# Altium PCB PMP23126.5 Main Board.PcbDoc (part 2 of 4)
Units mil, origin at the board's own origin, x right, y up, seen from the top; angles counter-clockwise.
Board outline 7480.32 x 4667 mil, 6 copper layers (Top Layer, Signal Layer 1, Signal Layer 2, Signal Layer 3, Signal Layer 4, Bottom Layer), stack 65.8 mil thick; 166 components, 83 nets, 633 pads, 4418 vias.
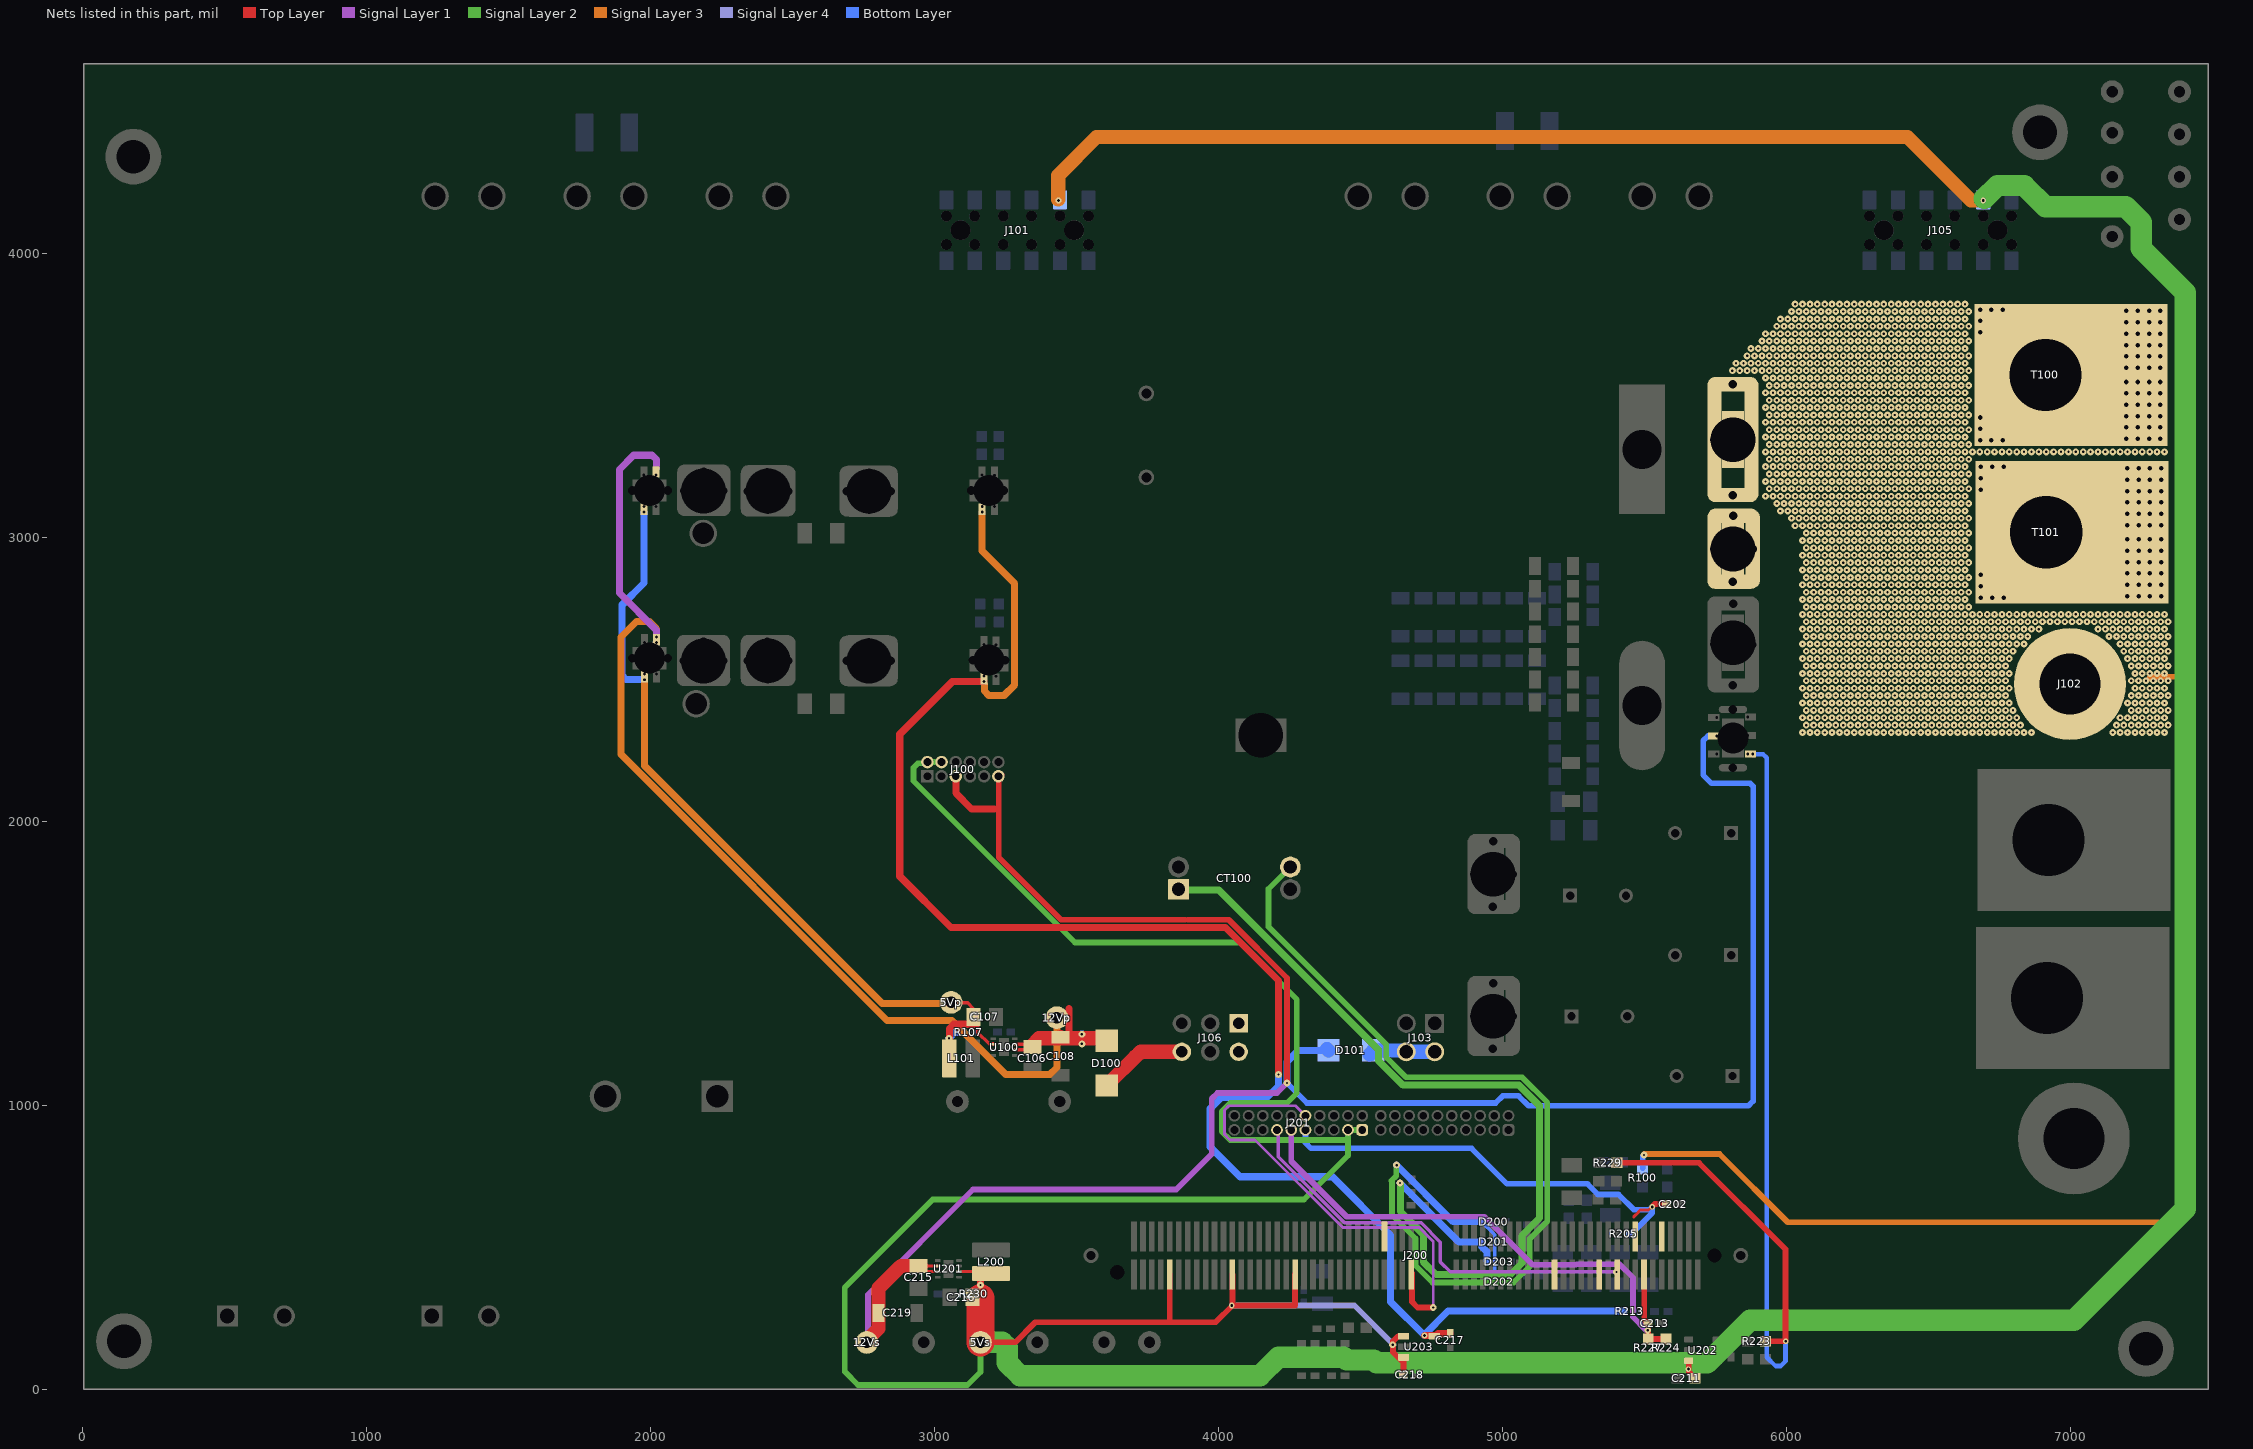
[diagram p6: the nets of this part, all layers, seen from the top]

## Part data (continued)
C205: library part CMP-0006320-2, "CAP, CERM, 470 pF, 50 V, +/- 10%, X7R, AEC-Q200 Grade 1, 0402", Cap_Case=0402, Manufacturer=TDK, Supplier Part Number 1=445-6888-1-ND, TempCo=X7R, Tolerance_%=10%, Value1="4.96489 ohm", Value2=50V, ValueDisplayed=470pF
C210 C214: "CAP, CERM, 1000pF, 50V, +/-10%, C0G/NP0, 0603", Cap_Case=0603, Manufacturer=AVX, Supplier Part Number 1=478-3718-1-ND, TempCo=C0G/NP0, Tolerance_%=10, Value1="0.048 ohm", Value2=50V, ValueDisplayed=1000pF
C211: "CAP, CERM, 1uF, 25V, +/-10%, X7R, 0603", Cap_Case=0603, Manufacturer=TDK, Supplier Part Number 1=445-5956-1-ND, TempCo=X7R, Tolerance_%=10, Value1=Unknown, Value2=25V, ValueDisplayed=1uF
C212: "CAP, CERM, 4.7 pF, 25 V,+/- 5%, C0G/NP0, 0402", Cap_Case=0402, Manufacturer=MuRata, Supplier Part Number 1=81-GRM1555C1E4R7CA1D, TempCo=C0G/NP0, Tolerance_%=5, Value2=25V, ValueDisplayed=4.7pF
C213: library part CMP-0064911-2, "CAP, CERM, 10 pF, 50 V,+/- 2.5%, C0G/NP0, AEC-Q200 Grade 1, 0402", Cap_Case=0402, Manufacturer=AVX, Supplier Part Number 1=478-5991-1-ND, TempCo=C0G/NP0, Tolerance_%=2.5%, Value1=Unknown, Value2=50V, ValueDisplayed=10pF
C217 C218: "CAP, CERM, 0.1uF, 6.3V, +/-10%, X7R, 0402", Cap_Case=0402, Manufacturer=MuRata, Supplier Part Number 1=GRM155R70J104KA01D-ND, TempCo=X7R, Tolerance_%=10, Value1=Unknown, Value2=6.3V, ValueDisplayed=0.1uF
C300 C301 C302 C303 C304 C315 C316 C317 C318 C319 C325 C326 C327 C328 C329 C330 C331 C332 C333 C334: library part CMP-0064950-2, "CAP, CERM, 0.1 uF, 25 V,+/- 5%, C0G/NP0, 1206", Cap_Case=1206, Manufacturer=MuRata, Supplier Part Number 1=490-1767-1-ND, TempCo=C0G/NP0, Tolerance_%=5%, Value1=Unknown, Value2=25V, ValueDisplayed=0.1uF
C305 C306 C307 C308 C309 C320 C321 C322 C323 C324: library part CMP-0008656-2, "CAP, CERM, 47 uF, 25 V, +/- 20%, X5R, 1206_190", Cap_Case=1206, Manufacturer=TDK, Supplier Part Number 1=445-8047-1-ND, TempCo=X5R, Tolerance_%=20%, Value1=Unknown, Value2=25V, ValueDisplayed=47uF
C310 C311 C312 C313 C314: library part CMP-0094633-1, "2200 µF 16 V Aluminum - Polymer Capacitors Radial, Can 8mOhm 20000 Hrs @ 105°C", Digikey Part Number=565-4315-ND, Leakage Current=7040uA, Manufacturer="United Chemi-Con", Mouser Part Number=661-APSG160E222MJ20S, Operating Temperature Range="-55°C to +105°C", Tolerance_%=20%, ValueDisplayed=2200uF
CT100: library part CMP-0091119-1, "Inductor PTH 3.3mH 300mOhm", Manufacturer="Pulse Electronics", Operating Temperature Range="-40°C to +125°C", Test Frequency=100kHz
D100 D101: library part CMP-0028374-2, "Diode, Schottky, 20 V, 1 A, SMA", Manufacturer="Diodes Inc.", Value1=1A, Value2=0.5V
D200 D201 D202 D203: "Diode, Ultrafast, 100 V, 0.25 A, SOD-323", Manufacturer=Nexperia, Supplier Part Number 1=568-5003-1-ND, Value1=0.25A, Value2=1.4V
J100: library part CMP-0094055-1, "12 Position Receptacle Connector 0.050\" (1.27mm) Through Hole Gold", Current_A=1A, Digikey Part Number=952-1366-5-ND, Manufacturer=Harwin, Mouser Part Number=855-M50-3000645, Operating Temperature Range="-40°C to +105°C"
J101 J105: library part CMP-0089984-1, "12 Position Receptacle, Bottom Entry Connector  Surface Mount", Current_A=4.1A, Digikey Part Number=HLE-106-02-G-DV-BE-A-ND, Manufacturer=Samtec, Mouser Part Number=200-HLE10602GDVBEA, Operating Temperature Range="-55°C to +125°C", Voltage_V=400V
J102 J104: library part CMP-0055165-2, "Standard Banana Jack, Uninsulated, 5.5mm", Manufacturer=Keystone, Supplier Part Number 1=36-575-4-ND
J103: library part CMP-0054598-1, "Header, 2.54mm, 2x2, Gold, TH", Color=Black, Current_A=3A, Manufacturer="Sullins Connector Solutions", Supplier Part Number 1=S2011E-02-ND, Voltage_V=1.8kV
J106: library part CMP-0054565-2, "Header, 100mil, 3x2, Gold, TH", Color=Black, Current_A=3A, Manufacturer="Sullins Connector Solutions", Supplier Part Number 1=S2011E-03-ND, Voltage_V=1.8kV
J200: library part controlCARD-120HSEC, "C2000 controlCARD-120HSEC connector, SMT", Manufacturer=Samtec
J201 J202: library part CMP-0750170-1, "Header, 1.27mm, 10x2, Gold, TH", Color=Black, Current_A=1A, Manufacturer="Sullins Connector Solutions", Voltage_V=500V
L100: library part CMP-0093530-1, "INDUCTOR, POWER, EP33, TH 0.42uH 20% 10kHz 0.06mOhm DCR MAX 300A Isat", Manufacturer=Pulse, Operating Temperature Range="-40°C to +125°C", Test Frequency=10kHz, Tolerance_%=20%
L101 L200: library part CMP-0087867-1, "2.2µH Shielded Molded Inductor 2.4A 67mOhm Max 2-SMD", Manufacturer="Wurth Electronics"
LEG1_HS LEG1_LS LEG2_HS LEG2_LS: "Test Point, Miniature, Yellow, TH", Color=Yellow, Manufacturer=Keystone, Supplier Part Number 1=36-5004-ND
LOGO100: library part CMP-0074837-1, "IEC 61010-1 Hot Surface Warning"
LOGO101: library part CMP-0074835-1, "IEC 61010-1 High Voltage Warning"
Logo102: library part CMP-0074847-1, "FCC_disclaimer"
Logo103: library part CMP-0074769-1
PGND PGND SGND SGND SGND SGND SGND101 SGND102 SGND103: "Test Point, Miniature, Black, TH", Color=Black, Manufacturer=Keystone, Supplier Part Number 1=36-5001-ND
PGND Vin: library part CMP-0055471-1, "Terminal Block, 5.08 mm, 2x1, TH", Color=Green, Current_A=17.5A, Manufacturer="Phoenix Contact", Supplier Part Number 1=277-1263-ND, Voltage_V=400V
PSON: "Test Point, Miniature, Orange, TH", Color=Orange, Manufacturer=Keystone, Supplier Part Number 1=36-5003-ND
R100 R101: "RES, 243, 1%, 0.1 W, 0603", Manufacturer=Vishay-Dale, Power_W=0.1, Supplier Part Number 1=541-243HCT-ND, TempCo="100 ppm/C", Tolerance_%=1, Value1=1%, Value2=0.1W, Value_Code=243R, ValueDisplayed=243
R102 R103: library part CMP-0018389-2, "RES, 5.11 k, 1%, 0.25 W, 1206", Manufacturer="Yageo America", Power_W=250mW, Supplier Part Number 1=311-5.11KFRCT-ND, TempCo="100 ppm/C", Tolerance_%=1%, Value2=0.25W, Value_Code=5k11, ValueDisplayed=5.11k
R104 R105 R106 R108: "RES, 0, 5%, 0.1 W, 0603", Manufacturer=Vishay-Dale, Power_W=0.1, Supplier Part Number 1=541-0.0GCT-ND, TempCo="200 ppm/C", Tolerance_%=5, Value1=5%, Value2=0.1W, Value_Code=0000, ValueDisplayed=0
R107 R230: library part CMP-0026504-2, "RES, 681 k, 1%, 0.063 W, AEC-Q200 Grade 0, 0402", Manufacturer=Vishay-Dale, Power_W=63mW, Supplier Part Number 1=541-681KLCT-ND, TempCo="100 ppm/C", Tolerance_%=1%, Value2=0.063W, Value_Code=681k
R109 R232: library part CMP-0025997-3, "RES, 130 k, 1%, 0.063 W, AEC-Q200 Grade 0, 0402", Manufacturer=Vishay-Dale, Power_W=63mW, Supplier Part Number 1=541-130KLCT-ND, TempCo="100 ppm/C", Tolerance_%=1%, Value2=0.063W, Value_Code=130k
R200 R203: "RES, 4.99 k, 1%, 0.063 W, 0402", Manufacturer=Vishay-Dale, Power_W=0.063, Supplier Part Number 1=541-4.99KLCT-ND, TempCo="100 ppm/C", Tolerance_%=1, Value1=1%, Value2=0.063W, Value_Code=4k99, ValueDisplayed=4.99k
R201 R204 R221 R229: "RES, 100, 1%, 0.1 W, 0603", Manufacturer=Vishay-Dale, Power_W=0.1, Supplier Part Number 1=541-100HCT-ND, TempCo="100 ppm/C", Tolerance_%=1, Value1=1%, Value2=0.1W, Value_Code=100R, ValueDisplayed=100
R202 R207: "RES, 9.31 k, 1%, 0.063 W, 0402", Manufacturer=Vishay-Dale, Power_W=0.063, Supplier Part Number 1=541-9.31KLCT-ND, TempCo="100 ppm/C", Tolerance_%=1, Value1=1%, Value2=0.063W, Value_Code=9k31, ValueDisplayed=9.31k
R205: "RES, 100, 1%, 0.125 W, AEC-Q200 Grade 1, 0402", Manufacturer="AT Ceramics", Power_W=0.125, TempCo=ppm/C, Tolerance_%=1, Value1=1%, Value2=0.125W, Value_Code=100R, ValueDisplayed=100
R206 R212: "RES, 0, 5%, 0.063 W, 0402", Manufacturer=Vishay-Dale, Power_W=0.063, Supplier Part Number 1=541-0.0JCT-ND, TempCo="200 ppm/C", Tolerance_%=5, Value1=5%, Value2=0.063W, Value_Code=0000, ValueDisplayed=0
R208 R209 R234 R235: "RES, 14.7, 1%, 0.25 W, 1206", Manufacturer=Vishay-Dale, Power_W=0.25, Supplier Part Number 1=541-14.7FCT-ND, TempCo="100 ppm/C", Tolerance_%=1, Value1=1%, Value2=0.25W, Value_Code=14R7, ValueDisplayed=14.7
R210: library part RC0603FR-079k76L, "RES, 9.76 k, 1%, 0.1 W, 0603", Manufacturer="Yageo America", Power_W=0.1, Supplier Part Number 1=311-9.76KHRCT-ND, TempCo="200 ppm/C", Tolerance_%=1, Value1=1%, Value2=0.1W, Value_Code=9k76, ValueDisplayed=9.76k
R211: "RES, 1.40k ohm, 1%, 0.063W, 0402", Manufacturer=Vishay-Dale, Power_W=0.063, Supplier Part Number 1=541-1.40KLCT-ND, TempCo="100 ppm/C", Tolerance_%=1, Value1=1%, Value2=0.063W, Value_Code=1k40
R213: "RES, 10.0 k, 1%, 0.063 W, 0402", Manufacturer=Vishay-Dale, Power_W=0.063, Supplier Part Number 1=541-10.0KLCT-ND, TempCo="100 ppm/C", Tolerance_%=1, Value1=1%, Value2=0.063W, Value_Code=10k0, ValueDisplayed=10.0k
R220 R228: "RES, 37.4 k, 1%, 0.25 W, 1206", Manufacturer=Vishay-Dale, Power_W=0.25, Supplier Part Number 1=541-37.4KFCT-ND, TempCo="100 ppm/C", Tolerance_%=1, Value1=1%, Value2=0.25W, Value_Code=37k4, ValueDisplayed=37.4k
R222 R231: "RES, 1.82 k, 1%, 0.1 W, 0603", Manufacturer="Yageo America", Power_W=0.1, Supplier Part Number 1=311-1.82KHRCT-ND, TempCo="200 ppm/C", Tolerance_%=1, Value1=1%, Value2=0.1W, Value_Code=1k82, ValueDisplayed=1.82k
R223 R226: "RES, 4.75, 1%, 0.1 W, 0603", Manufacturer="Yageo America", Power_W=0.1, Supplier Part Number 1=311-4.75HRCT-ND, TempCo="200 ppm/C", Tolerance_%=1, Value1=1%, Value2=0.1W, Value_Code=4R75, ValueDisplayed=4.75
R224: "RES, 2.49 k, 1%, 0.1 W, 0603", Manufacturer=Vishay-Dale, Power_W=0.1, Supplier Part Number 1=541-2.49KHCT-ND, TempCo="100 ppm/C", Tolerance_%=1, Value1=1%, Value2=0.1W, Value_Code=2k49, ValueDisplayed=2.49k
R225: "RES, 10.0 k, 1%, 0.25 W, 1206", Manufacturer=Vishay-Dale, Power_W=0.25, Supplier Part Number 1=541-10.0KFCT-ND, TempCo="100 ppm/C", Tolerance_%=1, Value1=1%, Value2=0.25W, Value_Code=10k0, ValueDisplayed=10.0k
R227: "RES, 7.50 k, 1%, 0.1 W, 0603", Manufacturer=Vishay-Dale, Power_W=0.1, Supplier Part Number 1=541-7.50KHCT-ND, TempCo="100 ppm/C", Tolerance_%=1, Value1=1%, Value2=0.1W, Value_Code=7k50, ValueDisplayed=7.50k
R233: "RES, 1.00 k, 1%, 0.063 W, 0402", Manufacturer=Vishay-Dale, Power_W=0.063, Supplier Part Number 1=541-1.00KLCT-ND, TempCo="100 ppm/C", Tolerance_%=1, Value1=1%, Value2=0.063W, Value_Code=1k00, ValueDisplayed=1.00k
RT200: library part CMP-0084566-1, "Thermistor, DEC0002A (X1SON-2)", Alternate Manufacturer="Texas Instruments", Alternate PartNumber=TMP6131DECT
T100 T101 T102 T103: library part CMP-0055443-2, "Terminal 90A Lug", Manufacturer=Panduit, Supplier Part Number 1=CB70-14-CY-ND, Voltage_V=600V
TP100 TP101 TP103 TP104 TP105 TP106 TP107 TP108 TP109 TP110 TP111 TP112 TP113 TP114: library part 0312-0-15-15-34-27-10-0, "Pin Receptacle, .032-.046\" .075\" Dia, Gold, TH", Manufacturer=Mill-Max, Supplier Part Number 1=0312-015153427100-ND
U100 U201: library part CMP-0067100-2, "3V-17V 1A Automotive Step-Down Converters in 2x2SON, DSG0008A (WSON-8)", Alternate Manufacturer="Texas Instruments", Alternate PartNumber=TPS62160QDSGTQ1
U202: library part CMP-0750220-2, "INA293 High-Voltage, High Bandwidth, Unidirectional, 110-V Common-Mode, Current-Sense Amplifier, DBV0005A (SOT-23-5)", Alternate Manufacturer="Texas Instruments", Alternate PartNumber=INA293B3IDBVT
U203: "Capacitor-Free, 150-mA, Low-Dropout Regulator with Foldback Current Limit for Portable Devices, DBV0005A", Alternate Manufacturer="Texas Instruments"

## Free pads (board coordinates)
  round 196.85 hole 118.11: 1(146,171) 1(179,4341) 1(6891,4427) 1(7264,144)
  round 0 hole 30 slot 110 at 90 deg unplated: 1(1935,2576) 1(1935,3166) 1(2060,2576) 1(2060,3166) 1(3128,3166) 1(3134,2569) 1(3243,3166) 1(3249,2569)
  rect 25x40 hole 10 copper offset 0,10: 1(1975.91,3220.88) 1(1977.91,2630.88) 1(2018.96,3220.88) 1(2020.96,2630.88) 1(3166.91,3220.88) 1(3172.91,2623.88) 1(3209.96,3219.88) 1(3215.96,2622.88)
  rect 25x40 hole 10 copper offset 0,-10: 1(1976.04,3110.12) 1(1978.04,2520.12) 1(2019.09,3110.12) 1(2021.09,2520.12) 1(3167.04,3110.12) 1(3173.04,2513.12) 1(3210.09,3109.12) 1(3216.09,2512.12)
  rect 118.11x78.74 hole 110 square unplated: 1(1996,2576) 1(1996,3166)
  oval 50x177.17 hole 30 slot 157.48 at 90 deg: 1(2117,2566) 1(2118,3165) 1(2255,2566) 1(2256,3165) 1(2342,2566) 1(2342,3163) 1(2485,2567) 1(2485,3164) 1(2690,2566) 1(2690,3163) 1(2845,2566) 1(2845,3163)
  rect 157.48x78.74 hole 157.48 square unplated: 1(2185.97,2565.41) 1(2185.97,3164.41) 1(2413,3164)
  oval 187.01x50 hole 30 slot 167.32 at 0 deg: 1(2186,2633) 1(2187,2502) 1(2187,3232) 1(2188,3101) 1(2411,2633) 1(2411,3230) 1(2412,2502) 1(2412,3099) 1(2767,2632) 1(2768,2501) 1(2769,3229) 1(2770,3098)
  rect 167.32x78.74 hole 157.48 square unplated: 1(2413,2567) 1(2769,2566) 1(2769,3163)
  rect 137.8x78.74 hole 110 square unplated: 1(3191,2569) 1(3191,3166)
  rect 179x118.11 hole 157.48 square unplated: 1(4148,2304)
  oval 50x275.59 hole 30 slot 255.91 at 90 deg: 1(4900,1315) 1(4900,1815) 1(5035,1315) 1(5035,1815) 1(5745,2960) 1(5880,2960)
  oval 177.17x50 hole 30 slot 157.48 at 0 deg: 1(4965,1200) 1(4965,1700) 1(4966,1432) 1(4966,1932) 1(5810,2480) 1(5810,2845) 1(5810,3150) 1(5810,3540) 1(5811,2768) 1(5811,3077)
  rect 78.74x200 hole 157.48 square unplated: 1(4965,1315) 1(4965,1815) 1(5810,2630) 1(5810,2960) 1(5810,3345)
  oval 50x334.65 hole 30 slot 314.96 at 90 deg: 1(5745,2625) 1(5877.57,2622.15)
  oval 50x433.07 hole 30 slot 413.39 at 90 deg: 1(5745,3345) 1(5875,3345)
  rect 40x25 hole 10 copper offset -10,0: 1(5753,2238.91) 1(5753,2301.96) 1(5753,2366.96)
  oval 100x25 hole 30 slot 110 at 0 deg unplated: 1(5810,2190) 1(5810,2395)
  rect 78.74x137.8 hole 110 square unplated: 1(5810,2295)
  rect 40x25 hole 10 copper offset 10,0: 1(5862,2238.04) 1(5862,2303.04) 1(5862,2368.04)

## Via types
v1: diameter 24, hole 8, Top Layer to Bottom Layer, 3810 vias
v2: diameter 32, hole 16, Top Layer to Bottom Layer, 232 vias
v3: diameter 24, hole 8, Top Layer to Bottom Layer, tented top, 210 vias
v4: diameter 20, hole 10, Top Layer to Bottom Layer, 76 vias
v5: diameter 20, hole 10, Top Layer to Bottom Layer, tented top, 57 vias
v6: diameter 24, hole 8, Top Layer to Bottom Layer, tented both sides, 29 vias
v7: diameter 19.68, hole 7.87, Top Layer to Bottom Layer, 4 vias

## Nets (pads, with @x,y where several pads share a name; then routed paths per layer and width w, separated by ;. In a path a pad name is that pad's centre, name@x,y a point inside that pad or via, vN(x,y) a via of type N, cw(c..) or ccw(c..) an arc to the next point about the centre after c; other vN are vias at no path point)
3V3s: C217.1 pad.1@3167.04,3110.12 pad.1@3173.04,2513.12 R213.1 U203.5 | length 5948.8
  Top Layer w25: v4(3173.04,2493) 3061.81,2493 2876.91,2308.09 2876.91,1808.09 3057.5,1627.5 4023.61,1627.5 4210,1441.11 v6(4210,1110) ; v4(4724.07,190.98) 4763.44,190.98 4771.31,198.85 C217.1@4814.62,198.85
  Signal Layer 3 w25: v4(3167.04,3090) 3167.04,2952.96 3281.5,2838.5 3281.5,2752.77 3281.5,2481.5 3245,2445 3189.64,2445 3175,2459.64 3175,2485 pad.1@3170,2490
  Bottom Layer w25: v6(4210,1110) 4210,1070 4170,1030 4010,1030 3970,990 3970,855 4075,750 4400,750 4605,545 4605,310.05 v4(4724.07,190.98) ; v4@4723,193 4807,277 R213.1@5423.38,277
5Vp: 5Vp.1 C107.1 L101.2 pad.1@1976.04,3110.12 pad.1@1978.04,2520.12 R107.2 U100.6 | length 2957.2
  Top Layer w12: 5Vp.1@3058,1364 3060,1362 3116,1362 3136,1342 3136,1303 C107.1@3134,1301 ; C107.1@3136,1297 3152,1281 3152,1257 3191.36,1217.64 3205.52,1217.64 U100.6@3206.6,1216.56
  Top Layer w25: L101.2@3051.66,1167 3051.66,1271.66 3067,1287 3137,1287 C107.1@3140,1290
  Signal Layer 2 w25: 5Vp.1@3058,1364 5Vp.1@3063,1359
  Signal Layer 3 w25: pad.1@1978.04,2520.12 v4(1978.04,2500) 1978.04,2196.96 2815,1360 5Vp.1@3060,1360
  Bottom Layer w25: pad.1@1975,2500 1913.51,2500 1899.76,2513.75 1899.76,2763.74 1976.04,2840.02 v4(1976.04,3090) ; v6(3050,1238) 3071,1259 R107.2@3097,1259 ; 5Vp.1@3053.5,1368.5 5Vp.1@3058,1364
5Vs: 5Vs.1 C211.2 C216.1 C218.1 J100.2 J100.4 J101.10 J105.10 J200.84 J200.98 J200.112 J201.1 J201.3 L200.2 R230.2 U201.6 U202.3 U203.1 U203.3 | length 21035.7
  Top Layer w10: U201.6@3085.57,416.09 L200.2@3148.48,416.09
  Top Layer w20: 5Vs.1@3161,167 3283.22,167 3353.96,237.74 3988.74,237.74 v4@4048,297 ; 3827,246 3827.57,246.57 J200.112@3827.57,406 ; v4(4045.8,296.63) v4@4046.17,297 ; J200.98@4048.05,406 4048.05,298.87 v4@4046.17,297 ; 4268,297 4266.65,297 ; J200.84@4268.52,406 4268.52,298.87 4266.65,297 ; C218.1@4649.27,57.12 4649.27,96.49 4613.57,132.19 4613.57,171.02 4631.55,189.01 U203.1@4650.25,189.01 ; C218.1@4650.25,58.1 U203.3@4650.25,114.2 ; v4@5654.19,64.01 C211.2@5668.95,49.24 ; v4@5654.19,72.87 U202.3@5654.19,102.39 ; v4@4046.17,297 v4@4048,297 ; v4@4048,297 4266.65,297
  Top Layer w25: 3161,322.31 3161,396.51 3171.49,407 L200.2@3173,407
  Top Layer w100: 5Vs.1@3161,167 3161,322.31
  Signal Layer 1 w20: 5Vs.1@3161,167 5Vs.1@3184,144
  Signal Layer 2 w20: J100.2@2969.79,2215.21 2970,2215.41 J100.2@2970,2220 ; J100.2@2970,2210 J100.2@2965.39,2205.39 ; J100.4@3020,2210 2975,2210 2970.39,2205.39 J100.2@2965.39,2205.39 ; 5Vs.1@3161,167 3161,63 3115,17 2730,17 2683,64 2683,360 2993,670 4300,670 4455,825 4455,910 J201.3@4460,915 ; 4444.33,879.33 4040.23,879.33 4010,909.56 4010,980 4040,1010 4240,1010 4275,1045 4275,1374.29 4074.29,1575 3493.79,1575 2925,2143.79 2925,2190 2940.39,2205.39 J100.2@2965.39,2205.39 ; J201.3@4455,915 J201.3@4460,915 ; J201.1@4500,915 J201.3@4460,915
  Signal Layer 2 w75: 5Vs.1@3161,167 3238,167 3255,150 3255,95 3300,50 4145,50 4210,115 4440,115 4450,105 4545,105 4555,95 5720,95 5870,245 7010.75,245 7402.5,636.75 7402.5,3863.25 7247.5,4018.25 7247.5,4110 7192.5,4165 6910,4165 6835,4240 6741.41,4240 v4@6695,4193.59
  Signal Layer 3 w50: v4@3435,4190 3435,4275 3570,4410 6425,4410 6648,4187 v4(6691,4187)
  Signal Layer 4 w20: v4(4045.8,296.63) 4477.37,296.63 v6@4615,159
  Bottom Layer w25: R230.2@3160.65,337.71 3161,338.06 v6@3161,363
  other v4: 5653.2,72.87 3436,4187
  other v6: 4612,159 3161,369
12VA: pad.1@5745,2960 pad.1@5810,2845 pad.1@5810,2960 pad.1@5811,3077 pad.1@5862,2238.04 pad.1@5880,2960 R223.1 R229.2 | length 3443.7
  Top Layer w20: R229.2@5400.99,799 5691,799 5995,495 v4@5995,175 ; R223.1@5932.73,171.29 v4(5995.72,171.29)
  Signal Layer 2 w20: pad.1@5862,2238.04 5879.5,2238.04 pad.1@5882,2235.54
  Bottom Layer w16: v4(5879.98,2238.04) 5915.96,2238.04 5929,2225 5929,114.94 5959.94,84 5978.7,84 5995,100.3 v4@5995,170
12VB: J102.1 pad.1@5745,3345 pad.1@5810,3150 pad.1@5810,3345 pad.1@5810,3540 pad.1@5875,3345 R100.1 T100.1 T101.1 | length 4039.3
  Signal Layer 3 w20: v6@5498,830 5763,830 6003,590 7340,590 7395,645 7395,2485 7370,2510 7280,2510 7275,2505
  Bottom Layer w20: R100.1@5493,781 5493,821.92 5497,825.92 v6(5497,827)
  other v1: 6055,2314 6081,2314 6107,2314 6133,2314 6159,2314 6185,2314 6211,2314 6237,2314 6263,2314 6289,2314 6315,2314 6341,2314 6367,2314 6393,2314 6419,2314 6445,2314 6471,2314 6497,2314 6523,2314 6549,2314 6575,2314 6601,2314 6627,2314 6653,2314 6679,2314 6705,2314 6731,2314 6757,2314 6783,2314 6809,2314 6835,2314 6861,2314 7147,2314 7173,2314 7199,2314 7225,2314 7251,2314 7277,2314 7303,2314 7329,2314 6068,2340 6094,2340 6120,2340 6146,2340 6172,2340 6198,2340 6224,2340 6250,2340 6276,2340 6302,2340 6328,2340 6354,2340 6380,2340 6406,2340 6432,2340 6458,2340 6484,2340 6510,2340 6536,2340 6562,2340 6588,2340 6614,2340 6640,2340 6666,2340 6692,2340 6718,2340 6744,2340 6770,2340 6796,2340 6822,2340 7160,2340 7186,2340 7212,2340 7238,2340 7264,2340 7290,2340 7316,2340 7342,2340 6055,2366 6081,2366 6107,2366 6133,2366 6159,2366 6185,2366 6211,2366 6237,2366 6263,2366 6289,2366 6315,2366 6341,2366 6367,2366 6393,2366 6419,2366 6445,2366 6471,2366 6497,2366 6523,2366 6549,2366 6575,2366 6601,2366 6627,2366 6653,2366 6679,2366 6705,2366 6731,2366 6757,2366 6783,2366 6809,2366 7173,2366 7199,2366 7225,2366 7251,2366 7277,2366 7303,2366 7329,2366 6068,2392 6094,2392 6120,2392 6146,2392 6172,2392 6198,2392 6224,2392 6250,2392 6276,2392 6302,2392 6328,2392 6354,2392 6380,2392 6406,2392 6432,2392 6458,2392 6484,2392 6510,2392 6536,2392 6562,2392 6588,2392 6614,2392 6640,2392 6666,2392 6692,2392 6718,2392 6744,2392 6770,2392 6796,2392 7212,2392 7238,2392 7264,2392 7290,2392 7316,2392 7342,2392 6055,2418 6081,2418 6107,2418 6133,2418 6159,2418 6185,2418 6211,2418 6237,2418 6263,2418 6289,2418 6315,2418 6341,2418 6367,2418 6393,2418 6419,2418 6445,2418 6471,2418 6497,2418 6523,2418 6549,2418 6575,2418 6601,2418 6627,2418 6653,2418 6679,2418 6705,2418 6731,2418 6757,2418 6783,2418 7199,2418 7225,2418 7251,2418 7277,2418 7303,2418 7329,2418 6068,2444 6094,2444 6120,2444 6146,2444 6172,2444 6198,2444 6224,2444 6250,2444 6276,2444 6302,2444 6328,2444 6354,2444 6380,2444 6406,2444 6432,2444 6458,2444 6484,2444 6510,2444 6536,2444 6562,2444 6588,2444 6614,2444 6640,2444 6666,2444 6692,2444 6718,2444 6744,2444 6770,2444 7212,2444 7238,2444 7264,2444 7290,2444 7316,2444 7342,2444 6055,2470 6081,2470 6107,2470 6133,2470 6159,2470 6185,2470 6211,2470 6237,2470 6263,2470 6289,2470 6315,2470 6341,2470 6367,2470 6393,2470 6419,2470 6445,2470 6471,2470 6497,2470 6523,2470 6549,2470 6575,2470 6601,2470 6627,2470 6653,2470 6679,2470 6705,2470 6731,2470 6757,2470 6783,2470 7225,2470 7251,2470 7277,2470 7303,2470 7329,2470 6068,2496 6094,2496 6120,2496 6146,2496 6172,2496 6198,2496 6224,2496 6250,2496 6276,2496 6302,2496 6328,2496 6354,2496 6380,2496 6406,2496 6432,2496 6458,2496 6484,2496 6510,2496 6536,2496 6562,2496 6588,2496 6614,2496 6640,2496 6666,2496 6692,2496 6718,2496 6744,2496 6770,2496 7212,2496 7238,2496 7264,2496 7290,2496 7316,2496 7342,2496 6055,2522 6081,2522 6107,2522 6133,2522 6159,2522 6185,2522 6211,2522 6237,2522 6263,2522 6289,2522 6315,2522 6341,2522 6367,2522 6393,2522 6419,2522 6445,2522 6471,2522 6497,2522 6523,2522 6549,2522 6575,2522 6601,2522 6627,2522 6653,2522 6679,2522 6705,2522 6731,2522 6757,2522 6783,2522 7225,2522 7251,2522 7277,2522 7303,2522 7329,2522 6068,2548 6094,2548 6120,2548 6146,2548 6172,2548 6198,2548 6224,2548 6250,2548 6276,2548 6302,2548 6328,2548 6354,2548 6380,2548 6406,2548 6432,2548 6458,2548 6484,2548 6510,2548 6536,2548 6562,2548 6588,2548 6614,2548 6640,2548 6666,2548 6692,2548 6718,2548 6744,2548 6770,2548 7212,2548 7238,2548 7264,2548 7290,2548 7316,2548 7342,2548 6055,2574 6081,2574 6107,2574 6133,2574 6159,2574 6185,2574 6211,2574 6237,2574 6263,2574 6289,2574 6315,2574 6341,2574 6367,2574 6393,2574 6419,2574 6445,2574 6471,2574 6497,2574 6523,2574 6549,2574 6575,2574 6601,2574 6627,2574 6653,2574 6679,2574 6705,2574 6731,2574 6757,2574 6783,2574 7199,2574 7225,2574 7251,2574 7277,2574 7303,2574 7329,2574 6068,2600 6094,2600 6120,2600 6146,2600 6172,2600 6198,2600 6224,2600 6250,2600 6276,2600 6302,2600 6328,2600 6354,2600 6380,2600 6406,2600 6432,2600 6458,2600 6484,2600 6510,2600 6536,2600 6562,2600 6588,2600 6614,2600 6640,2600 6666,2600 6692,2600 6718,2600 6744,2600 6770,2600 6796,2600 7186,2600 7212,2600 7238,2600 7264,2600 7290,2600 7316,2600 7342,2600 6055,2626 6081,2626 6107,2626 6133,2626 6159,2626 6185,2626 6211,2626 6237,2626 6263,2626 6289,2626 6315,2626 6341,2626 6367,2626 6393,2626 6419,2626 6445,2626 6471,2626 6497,2626 6523,2626 6549,2626 6575,2626 6601,2626 6627,2626 6653,2626 6679,2626 6705,2626 6731,2626 6757,2626 6783,2626 6809,2626 6835,2626 7173,2626 7199,2626 7225,2626 7251,2626 7277,2626 7303,2626 7329,2626 6068,2652 6094,2652 6120,2652 6146,2652 6172,2652 6198,2652 6224,2652 6250,2652 6276,2652 6302,2652 6328,2652 6354,2652 6380,2652 6406,2652 6432,2652 6458,2652 6484,2652 6510,2652 6536,2652 6562,2652 6588,2652 6614,2652 6640,2652 6666,2652 6692,2652 6718,2652 6744,2652 6770,2652 6796,2652 6822,2652 6848,2652 7134,2652 7160,2652 7186,2652 7212,2652 7238,2652 7264,2652 7290,2652 7316,2652 7342,2652 6055,2678 6081,2678 6107,2678 6133,2678 6159,2678 6185,2678 6211,2678 6237,2678 6263,2678 6289,2678 6315,2678 6341,2678 6367,2678 6393,2678 6419,2678 6445,2678 6471,2678 6497,2678 6523,2678 6549,2678 6575,2678 6601,2678 6627,2678 6653,2678 6679,2678 6705,2678 6731,2678 6757,2678 6783,2678 6809,2678 6835,2678 6861,2678 6887,2678 7095,2678 7121,2678 7147,2678 7173,2678 7199,2678 7225,2678 7251,2678 7277,2678 7303,2678 7329,2678 6068,2704 6094,2704 6120,2704 6146,2704 6172,2704 6198,2704 6224,2704 6250,2704 6276,2704 6302,2704 6328,2704 6354,2704 6380,2704 6406,2704 6432,2704 6458,2704 6484,2704 6510,2704 6536,2704 6562,2704 6588,2704 6614,2704 6640,2704 6666,2704 6692,2704 6718,2704 6744,2704 6770,2704 6796,2704 6822,2704 6848,2704 6874,2704 6900,2704 6926,2704 6952,2704 6978,2704 7004,2704 7030,2704 7056,2704 7082,2704 7108,2704 7134,2704 7160,2704 7186,2704 7212,2704 7238,2704 7264,2704 7290,2704 7316,2704 7342,2704 6055,2730 6081,2730 6107,2730 6133,2730 6159,2730 6185,2730 6211,2730 6237,2730 6263,2730 6289,2730 6315,2730 6341,2730 6367,2730 6393,2730 6419,2730 6445,2730 6471,2730 6497,2730 6523,2730 6549,2730 6575,2730 6601,2730 6627,2730 6653,2730 6679,2730 6705,2730 6731,2730 6757,2730 6783,2730 6809,2730 6835,2730 6861,2730 6887,2730 6913,2730 6939,2730 6965,2730 6991,2730 7017,2730 7043,2730 7069,2730 7095,2730 7121,2730 7147,2730 7173,2730 7199,2730 7225,2730 7251,2730 7277,2730 7303,2730 7329,2730 6068,2756 6094,2756 6120,2756 6146,2756 6172,2756 6198,2756 6224,2756 6250,2756 6276,2756 6302,2756 6328,2756 6354,2756 6380,2756 6406,2756 6432,2756 6458,2756 6484,2756 6510,2756 6536,2756 6562,2756 6588,2756 6614,2756 6640,2756 6055,2782 6081,2782 6107,2782 6133,2782 6159,2782 6185,2782 6211,2782 6237,2782 6263,2782 6289,2782 6315,2782 6341,2782 6367,2782 6393,2782 6419,2782 6445,2782 6471,2782 6497,2782 6523,2782 6549,2782 6575,2782 6601,2782 6627,2782 6068,2808 6094,2808 6120,2808 6146,2808 6172,2808 6198,2808 6224,2808 6250,2808 6276,2808 6302,2808 6328,2808 6354,2808 6380,2808 6406,2808 6432,2808 6458,2808 6484,2808 6510,2808 6536,2808 6562,2808 6588,2808 6614,2808 6640,2808 6055,2834 6081,2834 6107,2834 6133,2834 6159,2834 6185,2834 6211,2834 6237,2834 6263,2834 6289,2834 6315,2834 6341,2834 6367,2834 6393,2834 6419,2834 6445,2834 6471,2834 6497,2834 6523,2834 6549,2834 6575,2834 6601,2834 6627,2834 6068,2860 6094,2860 6120,2860 6146,2860 6172,2860 6198,2860 6224,2860 6250,2860 6276,2860 6302,2860 6328,2860 6354,2860 6380,2860 6406,2860 6432,2860 6458,2860 6484,2860 6510,2860 6536,2860 6562,2860 6588,2860 6614,2860 6640,2860 6055,2886 6081,2886 6107,2886 6133,2886 6159,2886 6185,2886 6211,2886 6237,2886 6263,2886 6289,2886 6315,2886 6341,2886 6367,2886 6393,2886 6419,2886 6445,2886 6471,2886 6497,2886 6523,2886 6549,2886 6575,2886 6601,2886 6627,2886 6068,2912 6094,2912 6120,2912 6146,2912 6172,2912 6198,2912 6224,2912 6250,2912 6276,2912 6302,2912 6328,2912 6354,2912 6380,2912 6406,2912 6432,2912 6458,2912 6484,2912 6510,2912 6536,2912 6562,2912 6588,2912 6614,2912 6640,2912 6055,2938 6081,2938 6107,2938 6133,2938 6159,2938 6185,2938 6211,2938 6237,2938 6263,2938 6289,2938 6315,2938 6341,2938 6367,2938 6393,2938 6419,2938 6445,2938 6471,2938 6497,2938 6523,2938 6549,2938 6575,2938 6601,2938 6627,2938 6068,2964 6094,2964 6120,2964 6146,2964 6172,2964 6198,2964 6224,2964 6250,2964 6276,2964 6302,2964 6328,2964 6354,2964 6380,2964 6406,2964 6432,2964 6458,2964 6484,2964 6510,2964 6536,2964 6562,2964 6588,2964 6614,2964 6640,2964 6055,2990 6081,2990 6107,2990 6133,2990 6159,2990 6185,2990 6211,2990 6237,2990 6263,2990 6289,2990 6315,2990 6341,2990 6367,2990 6393,2990 6419,2990 6445,2990 6471,2990 6497,2990 6523,2990 6549,2990 6575,2990 6601,2990 6627,2990 6068,3016 6094,3016 6120,3016 6146,3016 6172,3016 6198,3016 6224,3016 6250,3016 6276,3016 6302,3016 6328,3016 6354,3016 6380,3016 6406,3016 6432,3016 6458,3016 6484,3016 6510,3016 6536,3016 6562,3016 6588,3016 6614,3016 6640,3016 6029,3042 6055,3042 6081,3042 6107,3042 6133,3042 6159,3042 6185,3042 6211,3042 6237,3042 6263,3042 6289,3042 6315,3042 6341,3042 6367,3042 6393,3042 6419,3042 6445,3042 6471,3042 6497,3042 6523,3042 6549,3042 6575,3042 6601,3042 6627,3042 6016,3068 6042,3068 6068,3068 6094,3068 6120,3068 6146,3068 6172,3068 6198,3068 6224,3068 6250,3068 6276,3068 6302,3068 6328,3068 6354,3068 6380,3068 6406,3068 6432,3068 6458,3068 6484,3068 6510,3068 6536,3068 6562,3068 6588,3068 6614,3068 6640,3068 5977,3094 6003,3094 6029,3094 6055,3094 6081,3094 6107,3094 6133,3094 6159,3094 6185,3094 6211,3094 6237,3094 6263,3094 6289,3094 6315,3094 6341,3094 6367,3094 6393,3094 6419,3094 6445,3094 6471,3094 6497,3094 6523,3094 6549,3094 6575,3094 6601,3094 6627,3094 5964,3120 5990,3120 6016,3120 6042,3120 6068,3120 6094,3120 6120,3120 6146,3120 6172,3120 6198,3120 6224,3120 6250,3120 6276,3120 6302,3120 6328,3120 6354,3120 6380,3120 6406,3120 6432,3120 6458,3120 6484,3120 6510,3120 6536,3120 6562,3120 6588,3120 6614,3120 6640,3120 5925,3146 5951,3146 5977,3146 6003,3146 6029,3146 6055,3146 6081,3146 6107,3146 6133,3146 6159,3146 6185,3146 6211,3146 6237,3146 6263,3146 6289,3146 6315,3146 6341,3146 6367,3146 6393,3146 6419,3146 6445,3146 6471,3146 6497,3146 6523,3146 6549,3146 6575,3146 6601,3146 6627,3146 5938,3172 5964,3172 5990,3172 6016,3172 6042,3172 6068,3172 6094,3172 6120,3172 6146,3172 6172,3172 6198,3172 6224,3172 6250,3172 6276,3172 6302,3172 6328,3172 6354,3172 6380,3172 6406,3172 6432,3172 6458,3172 6484,3172 6510,3172 6536,3172 6562,3172 6588,3172 6614,3172 6640,3172 5925,3198 5951,3198 5977,3198 6003,3198 6029,3198 6055,3198 6081,3198 6107,3198 6133,3198 6159,3198 6185,3198 6211,3198 6237,3198 6263,3198 6289,3198 6315,3198 6341,3198 6367,3198 6393,3198 6419,3198 6445,3198 6471,3198 6497,3198 6523,3198 6549,3198 6575,3198 6601,3198 6627,3198 5938,3224 5964,3224 5990,3224 6016,3224 6042,3224 6068,3224 6094,3224 6120,3224 6146,3224 6172,3224 6198,3224 6224,3224 6250,3224 6276,3224 6302,3224 6328,3224 6354,3224 6380,3224 6406,3224 6432,3224 6458,3224 6484,3224 6510,3224 6536,3224 6562,3224 6588,3224 6614,3224 6640,3224 5925,3250 5951,3250 5977,3250 6003,3250 6029,3250 6055,3250 6081,3250 6107,3250 6133,3250 6159,3250 6185,3250 6211,3250 6237,3250 6263,3250 6289,3250 6315,3250 6341,3250 6367,3250 6393,3250 6419,3250 6445,3250 6471,3250 6497,3250 6523,3250 6549,3250 6575,3250 6601,3250 6627,3250 5938,3276 5964,3276 5990,3276 6016,3276 6042,3276 6068,3276 6094,3276 6120,3276 6146,3276 6172,3276 6198,3276 6224,3276 6250,3276 6276,3276 6302,3276 6328,3276 6354,3276 6380,3276 6406,3276 6432,3276 6458,3276 6484,3276 6510,3276 6536,3276 6562,3276 6588,3276 6614,3276 6640,3276 5925,3302 5951,3302 5977,3302 6003,3302 6029,3302 6055,3302 6081,3302 6107,3302 6133,3302 6159,3302 6185,3302 6211,3302 6237,3302 6263,3302 6289,3302 6315,3302 6341,3302 6367,3302 6393,3302 6419,3302 6445,3302 6471,3302 6497,3302 6523,3302 6549,3302 6575,3302 6601,3302 6627,3302 6653,3302 6679,3302 6705,3302 6731,3302 6757,3302 6783,3302 6809,3302 6835,3302 6861,3302 6887,3302 6913,3302 6939,3302 6965,3302 6991,3302 7017,3302 7043,3302 7069,3302 7095,3302 7121,3302 7147,3302 7173,3302 7199,3302 7225,3302 7251,3302 7277,3302 7303,3302 7329,3302 5938,3328 5964,3328 5990,3328 6016,3328 6042,3328 6068,3328 6094,3328 6120,3328 6146,3328 6172,3328 6198,3328 6224,3328 6250,3328 6276,3328 6302,3328 6328,3328 6354,3328 6380,3328 6406,3328 6432,3328 6458,3328 6484,3328 6510,3328 6536,3328 6562,3328 6588,3328 6614,3328 6640,3328 5925,3354 5951,3354 5977,3354 6003,3354 6029,3354 6055,3354 6081,3354 6107,3354 6133,3354 6159,3354 6185,3354 6211,3354 6237,3354 6263,3354 6289,3354 6315,3354 6341,3354 6367,3354 6393,3354 6419,3354 6445,3354 6471,3354 6497,3354 6523,3354 6549,3354 6575,3354 6601,3354 6627,3354 5938,3380 5964,3380 5990,3380 6016,3380 6042,3380 6068,3380 6094,3380 6120,3380 6146,3380 6172,3380 6198,3380 6224,3380 6250,3380 6276,3380 6302,3380 6328,3380 6354,3380 6380,3380 6406,3380 6432,3380 6458,3380 6484,3380 6510,3380 6536,3380 6562,3380 6588,3380 6614,3380 6640,3380 5925,3406 5951,3406 5977,3406 6003,3406 6029,3406 6055,3406 6081,3406 6107,3406 6133,3406 6159,3406 6185,3406 6211,3406 6237,3406 6263,3406 6289,3406 6315,3406 6341,3406 6367,3406 6393,3406 6419,3406 6445,3406 6471,3406 6497,3406 6523,3406 6549,3406 6575,3406 6601,3406 6627,3406 5938,3432 5964,3432 5990,3432 6016,3432 6042,3432 6068,3432 6094,3432 6120,3432 6146,3432 6172,3432 6198,3432 6224,3432 6250,3432 6276,3432 6302,3432 6328,3432 6354,3432 6380,3432 6406,3432 6432,3432 6458,3432 6484,3432 6510,3432 6536,3432 6562,3432 6588,3432 6614,3432 6640,3432 5925,3458 5951,3458 5977,3458 6003,3458 6029,3458 6055,3458 6081,3458 6107,3458 6133,3458 6159,3458 6185,3458 6211,3458 6237,3458 6263,3458 6289,3458 6315,3458 6341,3458 6367,3458 6393,3458 6419,3458 6445,3458 6471,3458 6497,3458 6523,3458 6549,3458 6575,3458 6601,3458 6627,3458 5938,3484 5964,3484 5990,3484 6016,3484 6042,3484 6068,3484 6094,3484 6120,3484 6146,3484 6172,3484 6198,3484 6224,3484 6250,3484 6276,3484 6302,3484 6328,3484 6354,3484 6380,3484 6406,3484 6432,3484 6458,3484 6484,3484 6510,3484 6536,3484 6562,3484 6588,3484 6614,3484 6640,3484 5925,3510 5951,3510 5977,3510 6003,3510 6029,3510 6055,3510 6081,3510 6107,3510 6133,3510 6159,3510 6185,3510 6211,3510 6237,3510 6263,3510 6289,3510 6315,3510 6341,3510 6367,3510 6393,3510 6419,3510 6445,3510 6471,3510 6497,3510 6523,3510 6549,3510 6575,3510 6601,3510 6627,3510 5938,3536 5964,3536 5990,3536 6016,3536 6042,3536 6068,3536 6094,3536 6120,3536 6146,3536 6172,3536 6198,3536 6224,3536 6250,3536 6276,3536 6302,3536 6328,3536 6354,3536 6380,3536 6406,3536 6432,3536 6458,3536 6484,3536 6510,3536 6536,3536 6562,3536 6588,3536 6614,3536 6640,3536 5925,3562 5951,3562 5977,3562 6003,3562 6029,3562 6055,3562 6081,3562 6107,3562 6133,3562 6159,3562 6185,3562 6211,3562 6237,3562 6263,3562 6289,3562 6315,3562 6341,3562 6367,3562 6393,3562 6419,3562 6445,3562 6471,3562 6497,3562 6523,3562 6549,3562 6575,3562 6601,3562 6627,3562 5808,3588 5834,3588 5860,3588 5886,3588 5912,3588 5938,3588 5964,3588 5990,3588 6016,3588 6042,3588 6068,3588 6094,3588 6120,3588 6146,3588 6172,3588 6198,3588 6224,3588 6250,3588 6276,3588 6302,3588 6328,3588 6354,3588 6380,3588 6406,3588 6432,3588 6458,3588 6484,3588 6510,3588 6536,3588 6562,3588 6588,3588 6614,3588 6640,3588 5821,3614 5847,3614 5873,3614 5899,3614 5925,3614 5951,3614 5977,3614 6003,3614 6029,3614 6055,3614 6081,3614 6107,3614 6133,3614 6159,3614 6185,3614 6211,3614 6237,3614 6263,3614 6289,3614 6315,3614 6341,3614 6367,3614 6393,3614 6419,3614 6445,3614 6471,3614 6497,3614 6523,3614 6549,3614 6575,3614 6601,3614 6627,3614 5860,3640 5886,3640 5912,3640 5938,3640 5964,3640 5990,3640 6016,3640 6042,3640 6068,3640 6094,3640 6120,3640 6146,3640 6172,3640 6198,3640 6224,3640 6250,3640 6276,3640 6302,3640 6328,3640 6354,3640 6380,3640 6406,3640 6432,3640 6458,3640 6484,3640 6510,3640 6536,3640 6562,3640 6588,3640 6614,3640 6640,3640 5873,3666 5899,3666 5925,3666 5951,3666 5977,3666 6003,3666 6029,3666 6055,3666 6081,3666 6107,3666 6133,3666 6159,3666 6185,3666 6211,3666 6237,3666 6263,3666 6289,3666 6315,3666 6341,3666 6367,3666 6393,3666 6419,3666 6445,3666 6471,3666 6497,3666 6523,3666 6549,3666 6575,3666 6601,3666 6627,3666 5912,3692 5938,3692 5964,3692 5990,3692 6016,3692 6042,3692 6068,3692 6094,3692 6120,3692 6146,3692 6172,3692 6198,3692 6224,3692 6250,3692 6276,3692 6302,3692 6328,3692 6354,3692 6380,3692 6406,3692 6432,3692 6458,3692 6484,3692 6510,3692 6536,3692 6562,3692 6588,3692 6614,3692 6640,3692 5925,3718 5951,3718 5977,3718 6003,3718 6029,3718 6055,3718 6081,3718 6107,3718 6133,3718 6159,3718 6185,3718 6211,3718 6237,3718 6263,3718 6289,3718 6315,3718 6341,3718 6367,3718 6393,3718 6419,3718 6445,3718 6471,3718 6497,3718 6523,3718 6549,3718 6575,3718 6601,3718 6627,3718 5964,3744 5990,3744 6016,3744 6042,3744 6068,3744 6094,3744 6120,3744 6146,3744 6172,3744 6198,3744 6224,3744 6250,3744 6276,3744 6302,3744 6328,3744 6354,3744 6380,3744 6406,3744 6432,3744 6458,3744 6484,3744 6510,3744 6536,3744 6562,3744 6588,3744 6614,3744 6640,3744 5977,3770 6003,3770 6029,3770 6055,3770 6081,3770 6107,3770 6133,3770 6159,3770 6185,3770 6211,3770 6237,3770 6263,3770 6289,3770 6315,3770 6341,3770 6367,3770 6393,3770 6419,3770 6445,3770 6471,3770 6497,3770 6523,3770 6549,3770 6575,3770 6601,3770 6627,3770 6016,3796 6042,3796 6068,3796 6094,3796 6120,3796 6146,3796 6172,3796 6198,3796 6224,3796 6250,3796 6276,3796 6302,3796 6328,3796 6354,3796 6380,3796 6406,3796 6432,3796 6458,3796 6484,3796 6510,3796 6536,3796 6562,3796 6588,3796 6614,3796 6640,3796 6029,3822 6055,3822 6081,3822 6107,3822 6133,3822 6159,3822 6185,3822 6211,3822 6237,3822 6263,3822 6289,3822 6315,3822 6341,3822 6367,3822 6393,3822 6419,3822 6445,3822 6471,3822 6497,3822 6523,3822 6549,3822 6575,3822 6601,3822 6627,3822
  other v2: 6683,2789 6723,2789 6763,2789 7198,2794 7238,2794 7278,2794 7318,2794 6683,2829 7198,2834 7238,2834 7278,2834 7318,2834 6683,2869 7198,2874 7238,2874 7278,2874 7318,2874 7198,2914 7238,2914 7278,2914 7318,2914 7198,2954 7238,2954 7278,2954 7318,2954 7198,2994 7238,2994 7278,2994 7318,2994 7198,3044 7238,3044 7278,3044 7318,3044 7198,3084 7238,3084 7278,3084 7318,3084 7198,3124 7238,3124 7278,3124 7318,3124 7198,3164 7238,3164 7278,3164 7318,3164 6683,3169 7198,3204 7238,3204 7278,3204 7318,3204 6683,3209 7198,3244 7238,3244 7278,3244 7318,3244 6683,3249 6723,3249 6763,3249 6680,3343 6720,3343 6760,3343 7195,3348 7235,3348 7275,3348 7315,3348 6680,3383 7195,3388 7235,3388 7275,3388 7315,3388 6680,3423 7195,3428 7235,3428 7275,3428 7315,3428 7195,3468 7235,3468 7275,3468 7315,3468 7195,3508 7235,3508 7275,3508 7315,3508 7195,3548 7235,3548 7275,3548 7315,3548 7195,3598 7235,3598 7275,3598 7315,3598 7195,3638 7235,3638 7275,3638 7315,3638 7195,3678 7235,3678 7275,3678 7315,3678 7195,3718 7235,3718 7275,3718 7315,3718 6680,3723 7195,3758 7235,3758 7275,3758 7315,3758 6680,3763 7195,3798 7235,3798 7275,3798 7315,3798 6680,3803 6720,3803 6760,3803
12VLS_EN: J200.58 J201.10 | length 1698
  Top Layer w20: J200.58@4680,410 4680,310 4700,290 v6(4755,290)
  Signal Layer 1 w10: J201.10@4305,965 4270,1000 4035,1000 4020,985 4020,900 4040,880 4127.37,880 4436.19,571.19 4699.69,571.19 4700,571.5 4705.87,571.5 4755,522.37 v6(4755,290)
12Vp: 12Vp.1 C106.1 C108.1 D100.1 pad.1@1935,2576 pad.1@2018.96,3220.88 pad.1@2020.96,2630.88 pad.1@2060,2576 U100.2 U100.3 | length 4093.7
  Top Layer w12: U100.2@3281.4,1196.87 3323.87,1196.87 C106.1@3324,1197 ; U100.3@3281.4,1216.56 3328.56,1216.56 C106.1@3329,1217
  Top Layer w25: C108.1@3473,1241 3473,1342
  Top Layer w50: C106.1@3342,1212 3367.58,1237.58 3439.65,1237.58 C108.1@3443,1240.93 3446.35,1237.58 3602.58,1237.58 D100.1@3605,1240
  Signal Layer 1 w25: pad.1@2020,3245 2020,3275 2005,3290 1940,3290 1890,3240 1890,2805 2020.91,2674.1 v4(2020.91,2650)
  Signal Layer 3 w25: pad.1@2020.96,2630.88 2020.96,2679.04 1995,2705 1950,2705 1895,2650 1895,2237.57 2832.57,1300 3060,1300 3250,1110 3405,1110 3430,1135 12Vp.1@3430,1290
  Signal Layer 4 w25: pad.1@2019.5,2631.34 pad.1@2020.96,2629.88
  Bottom Layer w50: 3518,1240 3521,1237
  other v6: 3518,1218 3518,1252
12Vp_1: D100.2 J106.6 | length 324.1
  Top Layer w50: D100.2@3599,1066 D100.2@3603.42,1070.42 ; D100.2@3600,1080 3613.74,1080 3706.26,1172.52 ; 3705,1170 3725,1190 J106.6@3870,1190
12Vp_h: J106.1
12Vs: 12Vs.1 C215.1 C219.1 D101.1 J100.5 J100.11 pad.1@5753,2301.96 U201.2 U201.3 | length 8055.5
  Top Layer w10: C215.1@2963.32,416.09 U201.3@3010.76,416.09 ; C215.1@2963.32,435.78 U201.2@3010.76,435.78
  Top Layer w20: J100.11@3235,2165 3225,2155 3225,1875 3445,1655 3880,1655 ; 3890,1655 4035,1655 4240,1450 v6(4240,1080)
  Top Layer w25: J100.5@3074,2160 3074.55,2159.45 3074.55,2100.45 3130,2045 3210,2045
  Top Layer w50: 12Vs.1@2755.13,168.42 2802.38,215.66 C219.1@2802.38,270.78 2802.38,357.39 2874.49,429.51 ; 2881.12,436.13 C215.1@2951.98,436.13
  Signal Layer 1 w20: 12Vs.1@2765,165 2765,335 3135,705 3850,705 3975,830 3975,1025 3995,1045 4205,1045 v6(4240,1080)
  Signal Layer 2 w25: 12Vs.1@2761,172 12Vs.1@2766,167
  Signal Layer 4 w25: J100.5@3074,2160 J100.5@3077.65,2156.35 ; J100.11@3224,2157 J100.11@3227,2160
  Bottom Layer w20: v6(4240,1080) 4310,1010 4974.64,1010 4999.64,1035 5055.36,1035 5090.36,1000 5864.64,1000 5881,1016.36 5881,2124.64 5870.64,2135 5734.64,2135 5705,2164.64 5705,2285 5721.96,2301.96 pad.1@5753,2301.96 ; D101.1@4381.26,1200 D101.1@4390,1200
  Bottom Layer w25: v6(4240,1080) 4240,1155 4280,1195 D101.1@4386.26,1195
  Bottom Layer w50: D101.1@4381.26,1200 D101.1@4386.26,1195
12VS_1: D101.2 J103.2 J103.4 | length 220.9
  Bottom Layer w50: D101.2@4531.37,1180.63 4538.74,1188 D101.2@4548,1188 ; D101.2@4543.74,1195 J103.4@4650,1195 ; J103.4@4665,1190 J103.2@4760,1190
ACTIVE_EMI_SENSE_PSFB: J200.34
AD_IBUS: J200.24
CS+: CT100.1 D201.2 D203.1 | length 3336.2
  Signal Layer 2 w25: CT100.1@3850,1760 4000,1760 4562.5,1197.5 4562.5,1158.61 4638.61,1082.5 4648.61,1072.5 5056.75,1072.5 5129.22,1000.03 5129.22,604.64 5067.61,543.04 5067.61,446.51 5026.66,405.55 4764.45,405.55 4720,450 4720,547.5 4640,627.5 v6@4640,725
  Bottom Layer w25: v6(4638,728) 4845,521 D201.2@4924.86,521 ; D201.2@4924.86,521.68 D201.2@4924.86,521 ; D203.1@4944,453 4944,486 4924.86,505.14 D201.2@4924.86,521
CS-: CT100.3 D200.2 D202.1 | length 3579.9
  Signal Layer 2 w20: CT100.3@4251.97,1840.55 4175,1763.58 4175,1630 4590,1215 4590,1170 4640,1120 4660,1100 5068.14,1100 5156.72,1011.42 5156.72,593.25 5095.11,531.65 5095.11,435.11 5038.05,378.05 4751.95,378.05 4692.5,437.5 4692.5,532.5 4610,615 4610,735 ; 4608.28,735 4608.28,736.47 4625,753.18 v6@4625,790
  Bottom Layer w12: D200.2@4924.86,592.55 4971,546.41 4971,390 4962,381 D202.1@4951,381
  Bottom Layer w25: v6(4626,791) 4825,592 D200.2@4925,592
DAC_OUT: J200.9
FAN_CTRL: J200.63
FAN_FB: J200.20 J201.13 | length 1498.7
  Top Layer w10: v6(5400,415) 5400,408.38 J200.20@5402.38,406
  Signal Layer 1 w12: J201.13@4210,910 4210,820 4442.5,587.5 4712.5,587.5 4780,520 4780,450 4815,415 v6(5400,415)
HSS: J106.2
IHV_FB: C202.1 J200.15 J201.9 R205.1 | length 1632.8
  Top Layer w10: 5461,609 5461,609.27 5477.02,625.29 5477.02,627.62 5482.88,633.48 5512.77,633.48 v4@5523.29,644
  Top Layer w20: v4@5526,645 5535,654 C202.1@5576.38,654
  Signal Layer 1 w20: J201.9@4305,920 J201.9@4307.53,917.47
  Bottom Layer w20: J201.9@4305,915 4305,870 4325,850 4890,850 5015,725 5297.77,725 5334.98,687.79 5407.21,687.79 5460.52,634.48 5516.48,634.48 v4(5526,644) 5526,622.83 5452.42,549.24 R205.1@5448.48,549.24 ; R205.1@5446,547 R205.1@5446.08,547.08
ILV_FB: C213.1 J200.14 J201.11 R224.2 R227.2 | length 1914.4
  Top Layer w20: 5497.97,351.53 5497.97,247.79 C213.1@5507.54,238.22 ; C213.1@5511.47,234.28 5511.47,183.1 5515.41,179.17 R224.2@5566.59,179.17
  Signal Layer 1 w20: J201.11@4255,915 4255,804.7 4450.22,609.48 4935.52,609.48 5105,440 5257.09,440 5259.09,442 5411.18,442 5458.09,395.09 5458.09,256.91 v6@5505,210
  other v6: 5510,210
